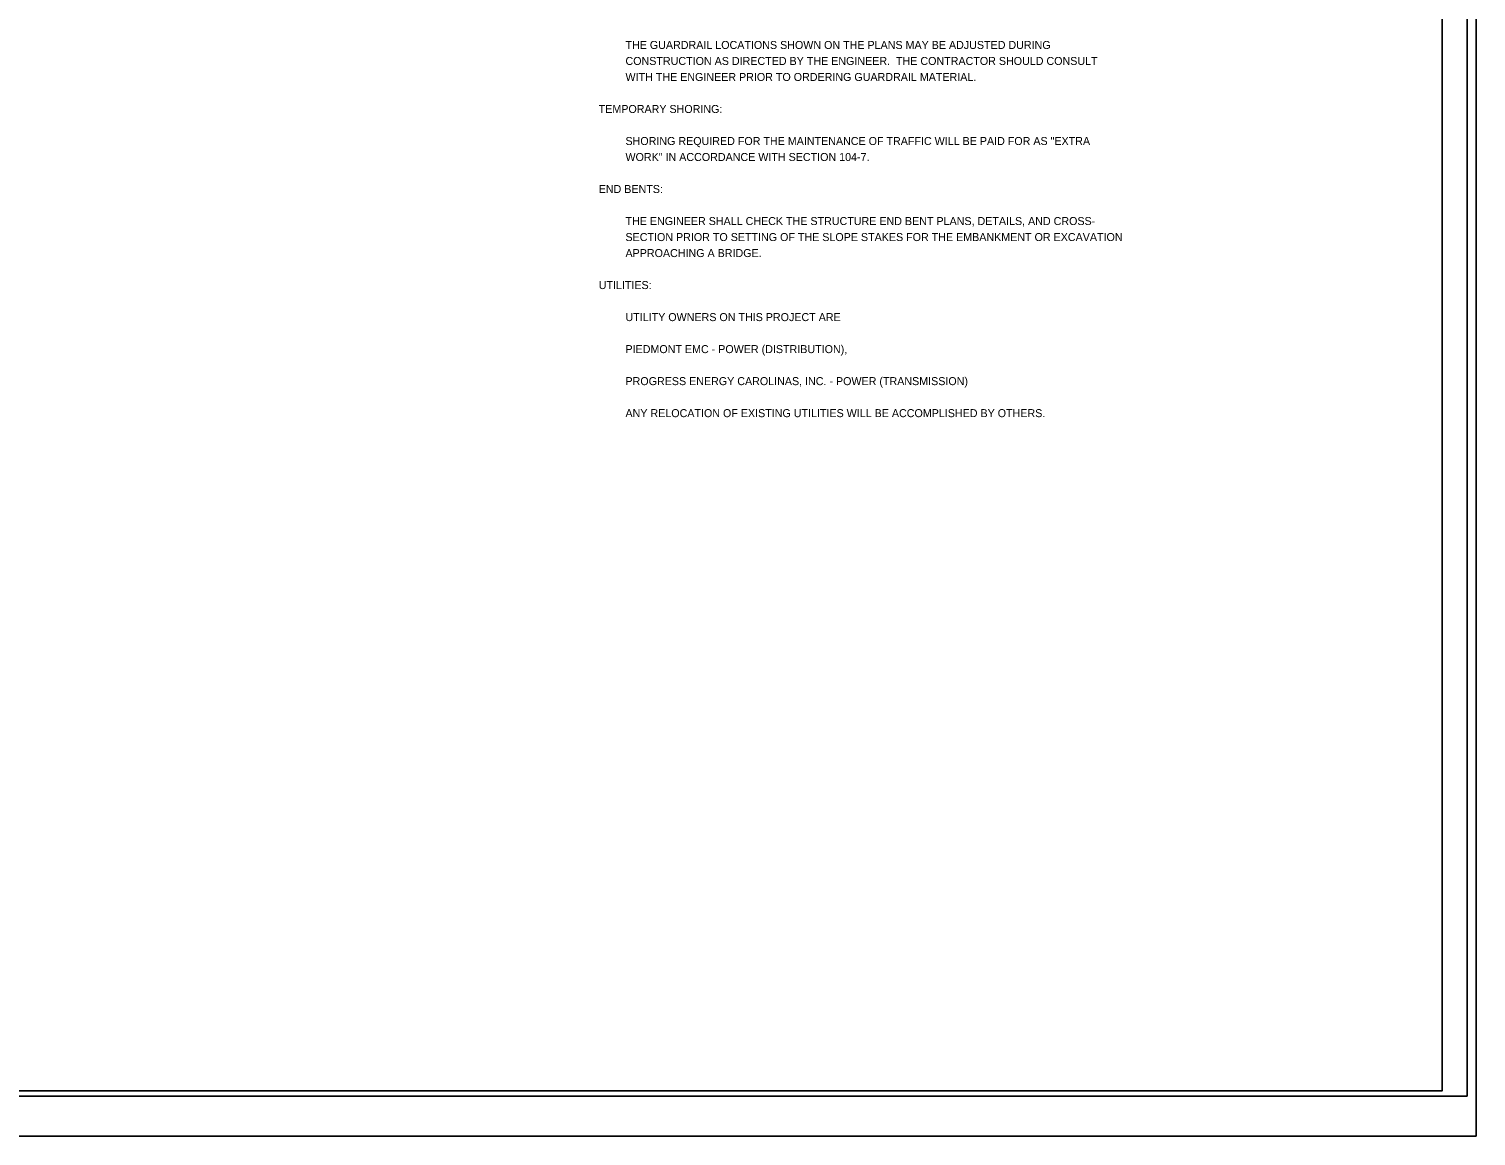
# Model space of a CAD drawing. Extents: x 573844.3 to 573878, y -53348.9 to -53327.
# Drawn here: x 573863.49 to 573877.96, y -53348.93 to -53337.87 of the extents above; entities that cross this region are included whole.
import ezdxf

# ---------------------------------------------------------------- set-up
doc = ezdxf.new("R2010")
doc.units = 0
for name, color, linetype in [('Default', 7, 'Continuous'), ('Sheet Cutting Line CELL', 7, 'Continuous'), ('Sheet Plan CELL', 7, 'Continuous'), ('Sheet Plot Border Inside CELL', 7, 'Continuous'), ('Sheet Plot Border Outside CELL', 7, 'Continuous')]:
    doc.layers.add(name, color=color, linetype=linetype)

msp = doc.modelspace()

# ---------------------------------------------------------------- linework, layer by layer
at = {"layer": 'Sheet Cutting Line CELL'}
msp.add_line((573844.289, -53348.932), (573877.959, -53348.932), dxfattribs=at)
at = {"layer": 'Sheet Plan CELL'}
msp.add_lwpolyline([(573877.619, -53327.482), (573847.619, -53327.482), (573847.619, -53348.482), (573877.619, -53348.482)], close=True, dxfattribs=at)
at = {"layer": 'Sheet Plot Border Inside CELL'}
msp.add_lwpolyline([(573844.549, -53348.532), (573877.869, -53348.532), (573877.869, -53327.432), (573844.549, -53327.432)], close=True, dxfattribs=at)
at = {"layer": 'Sheet Plot Border Outside CELL'}
msp.add_lwpolyline([(573844.289, -53348.932), (573877.959, -53348.932), (573877.959, -53327.032), (573844.289, -53327.032)], close=True, dxfattribs=at)

# ---------------------------------------------------------------- texts
at = {"layer": 'Default'}
for s, p in [('         THE GUARDRAIL LOCATIONS SHOWN ON THE PLANS MAY BE ADJUSTED DURING ', (573869.189, -53338.067)), ('         CONSTRUCTION AS DIRECTED BY THE ENGINEER.  THE CONTRACTOR SHOULD CONSULT', (573869.189, -53338.227)), ('         WITH THE ENGINEER PRIOR TO ORDERING GUARDRAIL MATERIAL.', (573869.189, -53338.387)), ('TEMPORARY SHORING:  ', (573869.189, -53338.707)), ('         SHORING REQUIRED FOR THE MAINTENANCE OF TRAFFIC WILL BE PAID FOR AS "EXTRA ', (573869.189, -53339.027)), ('         WORK" IN ACCORDANCE WITH SECTION 104-7.  ', (573869.189, -53339.187)), ('END BENTS:  ', (573869.189, -53339.507)), ('         THE ENGINEER SHALL CHECK THE STRUCTURE END BENT PLANS, DETAILS, AND CROSS-', (573869.189, -53339.827)), ('         SECTION PRIOR TO SETTING OF THE SLOPE STAKES FOR THE EMBANKMENT OR EXCAVATION ', (573869.189, -53339.987)), ('         APPROACHING A BRIDGE.  ', (573869.189, -53340.147)), ('UTILITIES:  ', (573869.189, -53340.467)), ('         UTILITY OWNERS ON THIS PROJECT ARE  ', (573869.189, -53340.787)), ('         PIEDMONT EMC - POWER (DISTRIBUTION), ', (573869.189, -53341.107)), ('         PROGRESS ENERGY CAROLINAS, INC. - POWER (TRANSMISSION)', (573869.189, -53341.427)), ('         ANY RELOCATION OF EXISTING UTILITIES WILL BE ACCOMPLISHED BY OTHERS.  ', (573869.189, -53341.747))]:
    msp.add_text(s, height=0.08, dxfattribs=at).set_placement(p)

doc.saveas('drawing.dxf')
